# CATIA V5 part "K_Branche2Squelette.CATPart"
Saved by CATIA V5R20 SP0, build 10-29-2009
Part number: Branche2(Squelette)
Publications: "Distance_Inter_Pivot", "Epaisseur_Cloison", "Encombrement_Lame", "Epaisseur_Branche", "Centre_Pivot_Branche2", "Plan_Branche2", "Point.3", "Droite.2", "Droite.4", "Droite.5"
Bounding box of the stored display mesh (mm): x -28.5 to -13.5, y 0 to 40, z 0 to 10
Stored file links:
  G:\Khaled_CFAO_2011\SIL\SIL_GR1\mneves\Khaled\CAD_CATIA_Modifie\K_Branche2Squelette.CATPart
  G:\Khaled_CFAO_2011\SIL\SIL_GR1\mneves\Khaled\CAD_CATIA_Modifie\K_SquePince_A_Bois.CATProduct
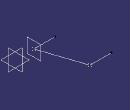
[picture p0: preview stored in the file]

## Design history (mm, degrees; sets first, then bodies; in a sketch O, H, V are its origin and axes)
External parameters (linked from other documents)
  External.Distance_Inter_Pivot = 200 mm
  External.Epaisseur_Cloison = 3 mm
  External.Encombrement_Lame = 12 mm
  External.Epaisseur_Branche = 15 mm
Set1
  Point1 "Centre_Pivot_Branche2": linked copy from another document
  Plane1 "Plan_Branche2": linked copy from another document
  Point2: linked copy from another document
Set2
  Line1: type Normal, RefPoint Point1, RefSkin Plane1, Start 0, End 15 {= External.Epaisseur_Branche}
  Line2: type PtPt, FirstPoint Point1, SecondPoint Point2
  Line3: type Normal, RefPoint Point2, RefSkin Plane1, Start 0, End 15 {= External.Epaisseur_Branche}
Body1 (main body)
